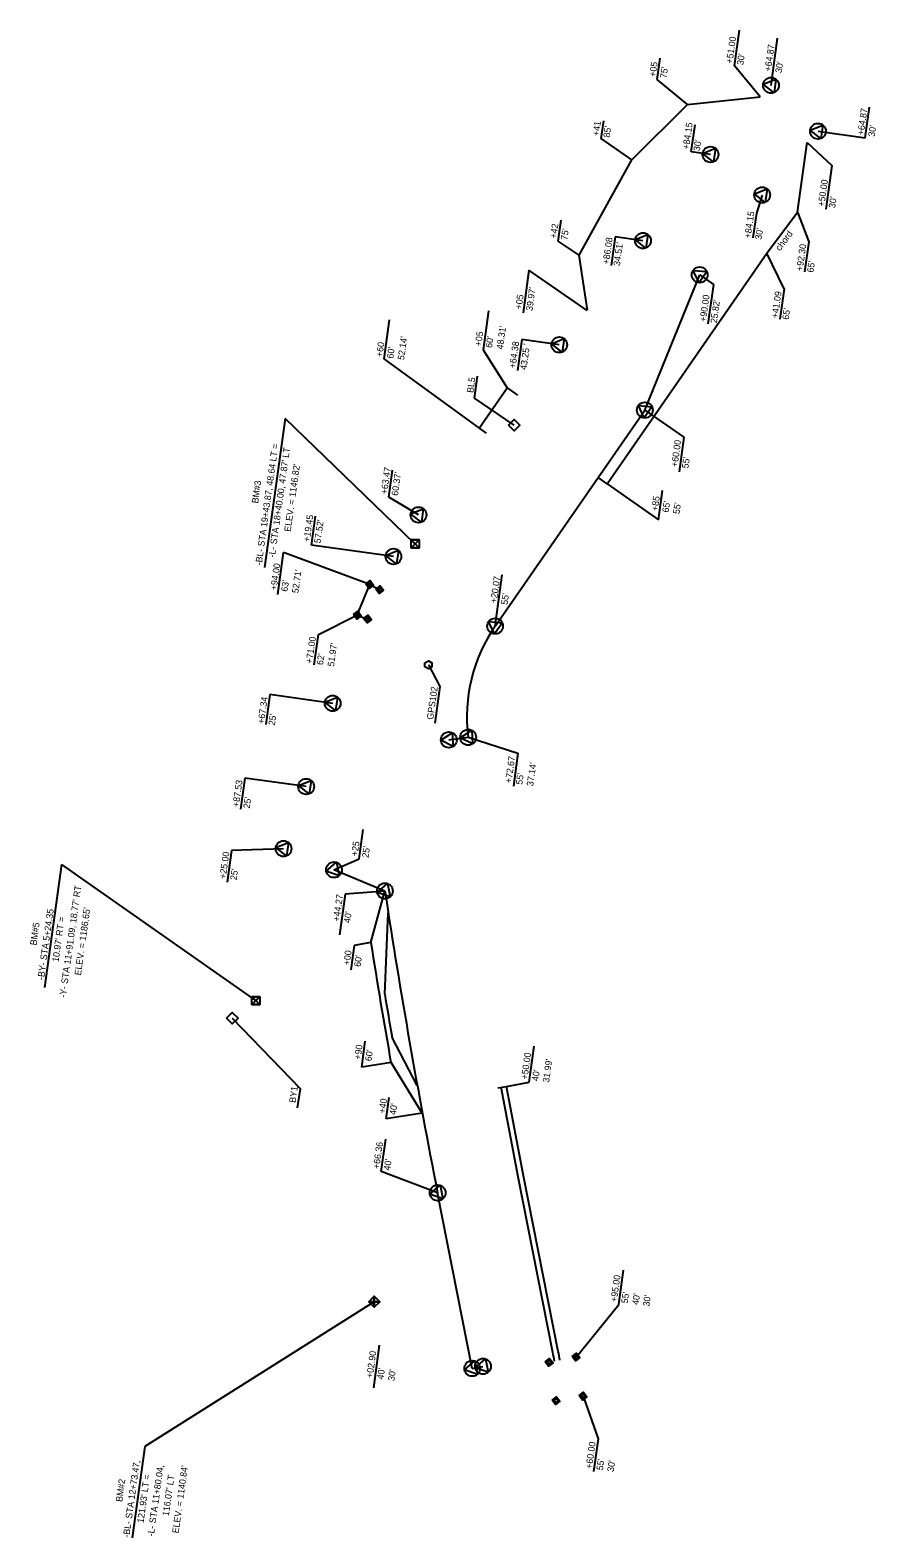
# Model space of a CAD drawing. Extents: x 1230900 to 1231672, y 678652 to 680028.
import ezdxf

# ---------------------------------------------------------------- set-up
doc = ezdxf.new("R2010")
doc.units = 0
for name, color, linetype in [('Default', 7, 'Continuous'), ('Prop Easement Construction', 7, 'Continuous'), ('Prop Easement Construction Station Offsets', 7, 'Continuous'), ('Prop Easement Permanent Drainage', 7, 'Continuous'), ('Prop Easement Permanent Drainage Station Offsets', 7, 'Continuous'), ('Prop RDY Alternate Text Yellow', 7, 'Continuous'), ('Prop ROW Marker CELL', 7, 'Continuous'), ('Prop ROW Permanent Easement CELL', 7, 'Continuous'), ('Prop ROW RW Lines', 7, 'Continuous'), ('Prop ROW Station Offsets', 7, 'Continuous'), ('Scratch_Level_0', 7, 'Continuous')]:
    doc.layers.add(name, color=color, linetype=linetype)

# ---------------------------------------------------------------- blocks, each defined once
blk = doc.blocks.new('CTL BENCH MARK')
at = {"layer": 'Default'}
blk.add_line((0, 0), (0, 0), dxfattribs=at)
blk.add_lwpolyline([(-0.072, 0.07175), (0.07175, 0.07175), (0.07175, -0.072), (-0.072, -0.072)], close=True, dxfattribs=at)
for points in [[(0.07175, 0.07175), (-0.072, -0.072), (-0.000125, -0.000125), (0.07175, -0.072), (-0.072, 0.07175)], [(-0.000125, -0.000125), (0.07175, 0.07175), (-0.072, 0.07175), (-0.000125, -0.000125)], [(-0.000125, -0.000125), (-0.072, -0.072), (0.07175, -0.072), (-0.000125, -0.000125)]]:
    blk.add_lwpolyline(points, dxfattribs=at)

msp = doc.modelspace()

# ---------------------------------------------------------------- linework, layer by layer
at = {"layer": 'Default'}
for p, q in [((1231341.9, 679667.9), (1231341.9, 679667.9)), ((1231251.5, 679559.6), (1231251.5, 679559.6)), ((1231263.6, 679449.2), (1231263.6, 679449.2)), ((1231105.9, 679142.6), (1231105.9, 679142.6)), ((1231084.5, 679126.7), (1231084.5, 679126.7))]:
    msp.add_line(p, q, dxfattribs=at)
for points in [[(1231336.7, 679667.9), (1231341.9, 679673.1), (1231347.2, 679667.9), (1231341.9, 679662.6)], [(1231247.9, 679563.1), (1231255.1, 679563.1), (1231255.1, 679556), (1231247.9, 679556)], [(1231260.4, 679451.1), (1231263.6, 679452.9), (1231266.9, 679451.1), (1231266.8, 679447.4), (1231263.6, 679445.5), (1231260.4, 679447.3)], [(1231102.3, 679146.2), (1231109.5, 679146.2), (1231109.5, 679139), (1231102.3, 679139)], [(1231079.2, 679126.7), (1231084.5, 679131.9), (1231089.7, 679126.7), (1231084.5, 679121.4)]]:
    msp.add_lwpolyline(points, close=True, dxfattribs=at)
for points in [[(1231255.1, 679563.1), (1231247.9, 679556), (1231251.5, 679559.6), (1231255.1, 679556), (1231247.9, 679563.1)], [(1231251.5, 679559.6), (1231255.1, 679563.1), (1231247.9, 679563.1), (1231251.5, 679559.6)], [(1231251.5, 679559.6), (1231247.9, 679556), (1231255.1, 679556), (1231251.5, 679559.6)], [(1231109.5, 679146.2), (1231102.3, 679139), (1231105.9, 679142.6), (1231109.5, 679139), (1231102.3, 679146.2)], [(1231105.9, 679142.6), (1231109.5, 679146.2), (1231102.3, 679146.2), (1231105.9, 679142.6)], [(1231105.9, 679142.6), (1231102.3, 679139), (1231109.5, 679139), (1231105.9, 679142.6)]]:
    msp.add_lwpolyline(points, dxfattribs=at)
at = {"layer": 'Prop Easement Construction'}
for p, q in [((1231449.5, 679910.2), (1231500.4, 679960.6)), ((1231500.4, 679960.6), (1231566.7, 679967.7)), ((1231600.8, 679862.2), (1231609.7, 679925.9)), ((1231401.3, 679823.2), (1231449.5, 679910.2)), ((1231572.8, 679824.8), (1231600.8, 679862.2)), ((1231409, 679772.8), (1231401.3, 679823.2)), ((1231426.9, 679614.4), (1231572.8, 679824.8)), ((1231309.9, 679665.1), (1231335.6, 679702)), ((1231335.6, 679702), (1231345.2, 679695.4)), ((1231309.9, 679665.1), (1231316.4, 679660.6)), ((1231426.9, 679614.4), (1231418.6, 679620.1)), ((1231211, 679195.6), (1231223.9, 679242.7)), ((1231258.1, 679040), (1231229.5, 679086.1)), ((1231327.1, 679062.9), (1231335, 679064.4)), ((1231350.5, 678982.7), (1231335, 679064.4)), ((1231382.2, 678822.4), (1231350.5, 678982.7))]:
    msp.add_line(p, q, dxfattribs=at)
for centre, radius, start, end in [((1237491.9, 680195.8), 6360, 189.04847, 190.04887), ((1229844.1, 678518.6), 1567.9, 10.8771, 11.1733)]:
    msp.add_arc(centre, radius, start, end, dxfattribs=at)
at = {"layer": 'Prop Easement Construction Station Offsets'}
for p, q in [((1231543.2, 679995.9), (1231547.8, 680028.5)), ((1231472.7, 679983.4), (1231475.4, 680002.8)), ((1231500.4, 679960.6), (1231472.7, 679983.4)), ((1231566.7, 679967.7), (1231543.2, 679995.9)), ((1231421.6, 679929.7), (1231423.8, 679945.7)), ((1231449.5, 679910.2), (1231421.6, 679929.7)), ((1231609.7, 679925.9), (1231632.3, 679904.8)), ((1231632.3, 679904.8), (1231626.8, 679865.2)), ((1231600.8, 679862.2), (1231611.2, 679835.4)), ((1231382.2, 679835.9), (1231384.9, 679854.9)), ((1231401.3, 679823.2), (1231382.2, 679835.9)), ((1231611.2, 679835.4), (1231607.3, 679807.8)), ((1231588.6, 679792.3), (1231572.8, 679824.8)), ((1231355.5, 679809.4), (1231350.1, 679770.5)), ((1231408.7, 679772.5), (1231355.5, 679809.4)), ((1231588.6, 679792.3), (1231584.8, 679764.7)), ((1231227.7, 679764.2), (1231222.8, 679728.5)), ((1231318.5, 679772.4), (1231313.6, 679736.8)), ((1231313.6, 679736.8), (1231335.6, 679702)), ((1231222.8, 679728.5), (1231309.9, 679665.1)), ((1231426.9, 679614.4), (1231473.8, 679581.4)), ((1231473.8, 679581.4), (1231477.6, 679608.2)), ((1231195.8, 679193.1), (1231192.7, 679170.6)), ((1231211, 679195.6), (1231195.8, 679193.1)), ((1231202.7, 679081.8), (1231206, 679105.7)), ((1231355.8, 679068.2), (1231360.4, 679101.2)), ((1231229.5, 679086.1), (1231202.7, 679081.8)), ((1231335, 679064.4), (1231355.8, 679068.2)), ((1231225.2, 679034.8), (1231227.9, 679054.3)), ((1231258.1, 679040), (1231225.2, 679034.8))]:
    msp.add_line(p, q, dxfattribs=at)
at = {"layer": 'Prop Easement Permanent Drainage'}
for p, q in [((1231198.7, 679494.5), (1231210, 679522.4)), ((1231210, 679522.4), (1231219.2, 679517.7)), ((1231198.7, 679494.5), (1231208.1, 679490.9))]:
    msp.add_line(p, q, dxfattribs=at)
at = {"layer": 'Prop Easement Permanent Drainage Station Offsets'}
for p, q in [((1231126.1, 679513.2), (1231131.4, 679551.8)), ((1231210, 679522.4), (1231131.4, 679551.8)), ((1231163.1, 679476.8), (1231198.8, 679494.8)), ((1231159.2, 679449), (1231163.1, 679476.8)), ((1231437.7, 678865.4), (1231442, 678896.5)), ((1231398.5, 678817.3), (1231437.7, 678865.4)), ((1231404.9, 678781.6), (1231418.8, 678742.5)), ((1231418.8, 678742.5), (1231414.6, 678712.7))]:
    msp.add_line(p, q, dxfattribs=at)
at = {"layer": 'Prop RDY Alternate Text Yellow'}
for p, q in [((1231305.8, 679692.7), (1231308.5, 679712.6)), ((1231341.9, 679667.9), (1231305.8, 679692.7)), ((1231132.8, 679674.1), (1231113.9, 679538.1)), ((1231251.1, 679559.8), (1231132.8, 679674.1)), ((1231263.6, 679449.2), (1231274.1, 679429.4)), ((1231274.1, 679429.4), (1231269.5, 679395.9)), ((1230913.3, 679154.6), (1230928.9, 679266.9)), ((1231105.9, 679142.6), (1230928.9, 679266.9)), ((1231084.5, 679126.7), (1231146.7, 679062.2)), ((1231144.2, 679044.7), (1231146.7, 679062.2)), ((1231214.2, 678867.8), (1231004.6, 678735.6)), ((1231004.6, 678735.6), (1230993, 678652.3))]:
    msp.add_line(p, q, dxfattribs=at)
at = {"layer": 'Prop ROW Marker CELL'}
for p, q in [((1231576.7, 679978.1), (1231576.7, 679978.1)), ((1231619.6, 679936.2), (1231619.6, 679936.2)), ((1231521.4, 679915), (1231521.4, 679915)), ((1231568.6, 679878), (1231568.6, 679878)), ((1231459.7, 679836.3), (1231459.7, 679836.3)), ((1231511.5, 679805.1), (1231511.5, 679805.1)), ((1231383.2, 679741.3), (1231383.2, 679741.3)), ((1231461.4, 679681.7), (1231461.4, 679681.7)), ((1231254.6, 679586), (1231254.6, 679586)), ((1231231.7, 679548), (1231231.7, 679548)), ((1231210, 679522.4), (1231210, 679522.4)), ((1231219.2, 679517.7), (1231219.2, 679517.7)), ((1231198.7, 679494.5), (1231198.7, 679494.5)), ((1231208.1, 679490.9), (1231208.1, 679490.9)), ((1231324.6, 679484.5), (1231324.6, 679484.5)), ((1231176.2, 679414), (1231176.2, 679414)), ((1231282.3, 679380.7), (1231282.3, 679380.7)), ((1231300, 679383), (1231300, 679383)), ((1231152, 679338), (1231152, 679338)), ((1231131.3, 679281.3), (1231131.3, 679281.3)), ((1231177.4, 679262.1), (1231177.4, 679262.1)), ((1231223.9, 679242.7), (1231223.9, 679242.7)), ((1231272.1, 678967.2), (1231272.1, 678967.2)), ((1231398.5, 678817.3), (1231398.5, 678817.3)), ((1231303.7, 678806.9), (1231303.7, 678806.9)), ((1231313.5, 678808.8), (1231313.5, 678808.8)), ((1231374, 678812.5), (1231374, 678812.5)), ((1231380.3, 678777.4), (1231380.3, 678777.4)), ((1231404.9, 678781.6), (1231404.9, 678781.6))]:
    msp.add_line(p, q, dxfattribs=at)
for points in [[(1231579.4, 679971.4), (1231569.6, 679979.1), (1231581.1, 679983.8)], [(1231622.3, 679929.5), (1231612.5, 679937.2), (1231624, 679941.9)], [(1231524.1, 679908.3), (1231514.2, 679916), (1231525.8, 679920.7)], [(1231571.3, 679871.3), (1231561.5, 679879), (1231573, 679883.7)], [(1231462.4, 679829.6), (1231452.6, 679837.3), (1231464.1, 679842)], [(1231510.9, 679797.9), (1231505.6, 679809.2), (1231518, 679808.2)], [(1231385.9, 679734.6), (1231376, 679742.3), (1231387.6, 679747)], [(1231460.8, 679674.5), (1231455.5, 679685.8), (1231467.9, 679684.8)], [(1231257.3, 679579.3), (1231247.4, 679587), (1231259, 679591.7)], [(1231234.4, 679541.3), (1231224.6, 679549), (1231236.2, 679553.7)], [(1231324, 679477.4), (1231318.7, 679488.7), (1231331.2, 679487.6)], [(1231178.9, 679407.4), (1231169.1, 679415), (1231180.6, 679419.7)], [(1231286.3, 679374.7), (1231275.1, 679380.3), (1231285.5, 679387.2)], [(1231304, 679377), (1231292.8, 679382.6), (1231303.2, 679389.5)], [(1231154.7, 679331.3), (1231144.9, 679339), (1231156.5, 679343.7)], [(1231134, 679274.7), (1231124.2, 679282.3), (1231135.7, 679287)], [(1231182.1, 679256.6), (1231170.4, 679260.8), (1231179.8, 679268.9)], [(1231228.6, 679237.3), (1231216.9, 679241.4), (1231226.3, 679249.5)], [(1231276.8, 678961.8), (1231265, 678965.9), (1231274.4, 678974.1)], [(1231308.4, 678801.4), (1231296.7, 678805.5), (1231306.1, 678813.7)], [(1231318.3, 678803.4), (1231306.5, 678807.5), (1231315.9, 678815.6)]]:
    msp.add_lwpolyline(points, close=True, dxfattribs=at)
for centre in [(1231576.7, 679978.1), (1231619.6, 679936.2), (1231521.4, 679915), (1231568.6, 679878), (1231459.7, 679836.3), (1231511.5, 679805.1), (1231383.2, 679741.3), (1231461.4, 679681.7), (1231254.6, 679586), (1231231.7, 679548), (1231324.6, 679484.5), (1231176.2, 679414), (1231282.3, 679380.7), (1231300, 679383), (1231152, 679338), (1231131.3, 679281.3), (1231177.4, 679262.1), (1231223.9, 679242.7), (1231272.1, 678967.2), (1231303.7, 678806.9), (1231313.5, 678808.8)]:
    msp.add_circle(centre, 7.2, dxfattribs=at)
at = {"layer": 'Prop ROW Permanent Easement CELL'}
for points in [[(1231206.5, 679522.9), (1231210.5, 679526), (1231213.6, 679521.9), (1231209.5, 679518.9)], [(1231208.2, 679522.7), (1231210.3, 679524.2), (1231211.8, 679522.2), (1231209.8, 679520.7)], [(1231215.6, 679518.2), (1231219.7, 679521.3), (1231222.7, 679517.2), (1231218.7, 679514.2)], [(1231217.4, 679518), (1231219.4, 679519.5), (1231221, 679517.5), (1231218.9, 679515.9)], [(1231195.1, 679495), (1231199.2, 679498), (1231202.2, 679494), (1231198.2, 679490.9)], [(1231196.9, 679494.7), (1231198.9, 679496.3), (1231200.5, 679494.2), (1231198.4, 679492.7)], [(1231204.5, 679491.4), (1231208.6, 679494.5), (1231211.6, 679490.4), (1231207.6, 679487.4)], [(1231206.3, 679491.2), (1231208.3, 679492.7), (1231209.8, 679490.7), (1231207.8, 679489.1)], [(1231370.4, 678813), (1231374.4, 678816.1), (1231377.5, 678812), (1231373.5, 678809)], [(1231372.2, 678812.8), (1231374.2, 678814.3), (1231375.7, 678812.3), (1231373.7, 678810.8)], [(1231394.9, 678817.8), (1231399, 678820.8), (1231402.1, 678816.8), (1231398, 678813.7)], [(1231396.7, 678817.5), (1231398.8, 678819), (1231400.3, 678817), (1231398.3, 678815.5)], [(1231376.7, 678777.9), (1231380.8, 678781), (1231383.8, 678776.9), (1231379.8, 678773.9)], [(1231378.5, 678777.7), (1231380.5, 678779.2), (1231382.1, 678777.2), (1231380, 678775.6)], [(1231401.4, 678782.1), (1231405.4, 678785.1), (1231408.5, 678781.1), (1231404.4, 678778)], [(1231403.2, 678781.8), (1231405.2, 678783.4), (1231406.7, 678781.3), (1231404.7, 678779.8)]]:
    msp.add_lwpolyline(points, close=True, dxfattribs=at)
at = {"layer": 'Prop ROW RW Lines'}
for p, q in [((1231461.4, 679681.7), (1231511.5, 679805.1)), ((1231324.6, 679484.5), (1231461.4, 679681.7)), ((1231282.3, 679380.7), (1231300, 679383)), ((1231223.9, 679242.7), (1231177.4, 679262.1)), ((1231303.7, 678806.9), (1231272.1, 678967.2)), ((1231303.7, 678806.9), (1231313.5, 678808.8))]:
    msp.add_line(p, q, dxfattribs=at)
for centre, radius, start, end in [((1231443.8, 679401.9), 145, 145.2492, 187.4781), ((1237491.9, 680195.8), 6340, 188.64585, 191.17333)]:
    msp.add_arc(centre, radius, start, end, dxfattribs=at)
at = {"layer": 'Prop ROW Station Offsets'}
for p, q in [((1231576.7, 679978.1), (1231582.7, 680021.2)), ((1231662.6, 679930.2), (1231666.5, 679958.2)), ((1231503.8, 679917.4), (1231507.3, 679942.2)), ((1231619.6, 679936.2), (1231662.6, 679930.2)), ((1231521.4, 679915), (1231503.8, 679917.4)), ((1231568.6, 679878), (1231563.4, 679861.5)), ((1231563.4, 679861.5), (1231560.2, 679838.8)), ((1231434.2, 679839.8), (1231430.5, 679813.6)), ((1231459.7, 679836.3), (1231434.2, 679839.8)), ((1231511.5, 679805.1), (1231524, 679796.4)), ((1231524, 679796.4), (1231519, 679760.4)), ((1231349, 679746), (1231345.1, 679717.8)), ((1231383.2, 679741.3), (1231349, 679746)), ((1231461.4, 679681.7), (1231497.1, 679656.9)), ((1231497.1, 679656.9), (1231492.7, 679625.2)), ((1231227.6, 679602.1), (1231231, 679626.7)), ((1231254.6, 679586), (1231227.6, 679602.1)), ((1231156.9, 679558.4), (1231160.6, 679584.8)), ((1231231.7, 679548), (1231156.9, 679558.4)), ((1231324.6, 679484.5), (1231331.1, 679531.3)), ((1231118.8, 679422), (1231115, 679394.8)), ((1231176.2, 679414), (1231118.8, 679422)), ((1231300, 679383), (1231345.5, 679368.6)), ((1231345.5, 679368.6), (1231341.3, 679338.3)), ((1231096, 679345.8), (1231092.1, 679317.5)), ((1231152, 679338), (1231096, 679345.8)), ((1231200.4, 679272), (1231204.1, 679298.9)), ((1231131.3, 679281.3), (1231083.9, 679279.8)), ((1231083.9, 679279.8), (1231079.9, 679250.8)), ((1231177.4, 679262.1), (1231200.4, 679272)), ((1231187.5, 679239.7), (1231182.4, 679202.7)), ((1231187.5, 679239.7), (1231183.8, 679213.4)), ((1231223.9, 679242.7), (1231187.5, 679239.7)), ((1231220.6, 678986.8), (1231224.7, 679016.1)), ((1231272.1, 678967.2), (1231220.6, 678986.8)), ((1231213.7, 678789.1), (1231219.1, 678828.2))]:
    msp.add_line(p, q, dxfattribs=at)
at = {"layer": 'Scratch_Level_0'}
for p, q in [((1231223.8, 679148.6), (1231227, 679222.7)), ((1231253.5, 679065.3), (1231230.5, 679109.1)), ((1231345.6, 678981.8), (1231330.1, 679063.5)), ((1231377.3, 678821.4), (1231345.6, 678981.8))]:
    msp.add_line(p, q, dxfattribs=at)
for centre, radius, start, end in [((1237491.9, 680195.8), 6355, 189.48454, 189.84616), ((1229844.1, 678518.6), 1562.9, 10.8771, 11.1733)]:
    msp.add_arc(centre, radius, start, end, dxfattribs=at)

# ---------------------------------------------------------------- block references
at = {"layer": 'Default', "xscale": 50, "yscale": 49.99999999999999, "rotation": 44.99999999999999}
msp.add_blockref('CTL BENCH MARK', (1231214.2, 678867.8), dxfattribs=at)

# ---------------------------------------------------------------- texts
at = {"layer": 'Prop Easement Construction'}
msp.add_text('chord', height=6, rotation=53.2649, dxfattribs=at).set_placement((1231584.9, 679826.5))
at = {"layer": 'Prop Easement Construction Station Offsets'}
for s, p in [('+51.00', (1231541.4, 679997.7)), ('+05', (1231471.3, 679985.7)), ("30'", (1231551.3, 679996.3)), ("75'", (1231481.2, 679984.3)), ('+41', (1231419.4, 679931.6)), ("85'", (1231429.3, 679930.2)), ('+50.00', (1231625.3, 679867.2)), ("30'", (1231635.2, 679865.8)), ('+42', (1231380.6, 679838)), ("75'", (1231390.5, 679836.6)), ('+92.30', (1231605.5, 679808.3)), ("65'", (1231615.4, 679807)), ("39.97'", (1231358.7, 679771.9)), ('+05', (1231348.8, 679773.3)), ('+41.09', (1231582.9, 679765.2)), ("65'", (1231592.8, 679763.9)), ("52.14'", (1231241.4, 679727.1)), ('+05', (1231311.9, 679739.6)), ("60'", (1231321.8, 679738.2)), ("48.31'", (1231331.7, 679736.8)), ('+60', (1231221.6, 679729.9)), ("60'", (1231231.5, 679728.5)), ('+85', (1231473.2, 679589.3)), ("65'", (1231483.1, 679587.9)), ("55'", (1231493, 679586.5)), ('+00', (1231191.7, 679174.6)), ("60'", (1231201.6, 679173.2)), ('+90', (1231201.7, 679088.5)), ("60'", (1231211.6, 679087.1)), ('+50.00', (1231354.1, 679070.3)), ("31.99'", (1231373.9, 679067.5)), ("40'", (1231364, 679068.9)), ('+40', (1231224, 679039.4)), ("40'", (1231233.9, 679038))]:
    msp.add_text(s, height=6, rotation=82.0744, dxfattribs=at).set_placement(p)
at = {"layer": 'Prop Easement Permanent Drainage Station Offsets'}
for s, p in [('+94.00', (1231125, 679516.9)), ("52.71'", (1231144.8, 679514.2)), ("63'", (1231134.9, 679515.6)), ('+71.00', (1231157.5, 679450)), ("51.97'", (1231177.4, 679447.3)), ("62'", (1231167.4, 679448.7)), ('+95.00', (1231435.8, 678867.3)), ("55'", (1231445.7, 678866)), ("40'", (1231455.6, 678864.6)), ("30'", (1231465.5, 678863.2)), ('+60.00', (1231413.1, 678715)), ("55'", (1231423, 678713.6)), ("30'", (1231432.9, 678712.2))]:
    msp.add_text(s, height=6, rotation=82.0744, dxfattribs=at).set_placement(p)
at = {"layer": 'Prop RDY Alternate Text Yellow'}
for s, p in [('BL5', (1231304.6, 679697.1)), ('-BL- STA 19+43.87, 48.64 LT =', (1231111.3, 679539.7)), ("-L- STA 18+40.00, 47.87' LT", (1231123.4, 679546.9)), ("ELEV. = 1146.82'", (1231137.8, 679570.4)), ('BM#3', (1231108.1, 679596.2)), ('GPS102 ', (1231268, 679398.8)), ("-Y- STA 11+91.09, 18.77' RT", (1230932.3, 679144.9)), ('-BY- STA 5+24.35', (1230912.4, 679161.2)), ("ELEV. = 1186.65'", (1230946.2, 679165.4)), ('BM#5', (1230905.6, 679192.8)), ("10.97' RT =", (1230925.8, 679177.7)), ('BY1 ', (1231142.3, 679049.1)), ('-BL- STA 12+73.47,', (1230990.4, 678652.2)), ('-L- STA 11+80.04,', (1231012.8, 678653.3)), ("ELEV. = 1140.84'", (1231035.4, 678656.1)), ('BM#2', (1230983.9, 678684.8)), ("121.93' LT = ", (1231003.4, 678665.6)), ("116.07' LT", (1231026.5, 678671.9))]:
    msp.add_text(s, height=6, rotation=82.0744, dxfattribs=at).set_placement(p)
at = {"layer": 'Prop ROW Station Offsets'}
for s, p in [('+64.87', (1231576.5, 679990.5)), ("30'", (1231586.4, 679989.1)), ('+64.87', (1231661.4, 679932.3)), ('+84.15', (1231501.7, 679919.2)), ("30'", (1231671.3, 679930.9)), ("30'", (1231511.6, 679917.8)), ('+84.15', (1231558.1, 679838.2)), ("30'", (1231568, 679836.9)), ('+86.08', (1231428.6, 679814.4)), ("34.51'", (1231438.5, 679813)), ('+90.00', (1231517.2, 679762)), ("25.82'", (1231527.1, 679760.7)), ('+64.38', (1231343.2, 679719.5)), ('43.25', (1231353.2, 679718.1)), ("'", (1231356.3, 679740.4)), ('+60.00', (1231491.2, 679629.5)), ("55'", (1231501.1, 679628.2)), ('+63.47', (1231225.9, 679604.6)), ("60.37'", (1231235.8, 679603.2)), ('+19.45', (1231155.2, 679561.2)), ("57.52'", (1231165.1, 679559.8)), ('+20.07', (1231326, 679505.1)), ("55'", (1231335.9, 679503.7)), ('+67.34', (1231113.5, 679395)), ("25'", (1231123.4, 679393.6)), ('+72.67', (1231339.5, 679340.8)), ("55'", (1231349.4, 679339.5)), ("37.14'", (1231359.3, 679338.1)), ('+87.53', (1231090.5, 679319.1)), ("25'", (1231100.4, 679317.8)), ('+25', (1231198.9, 679274.2)), ("25'", (1231208.9, 679272.8)), ('+25.00', (1231078.5, 679253.6)), ("25'", (1231088.4, 679252.3)), ('+44.27', (1231182.3, 679214.6)), ("40'", (1231192.2, 679213.2)), ('+66.36', (1231218.8, 678988.7)), ("40'", (1231228.7, 678987.3)), ('+02.90', (1231212.7, 678797.9)), ("40'", (1231222.6, 678796.6)), ("30'", (1231232.5, 678795.2))]:
    msp.add_text(s, height=6, rotation=82.0744, dxfattribs=at).set_placement(p)

doc.saveas('drawing.dxf')
